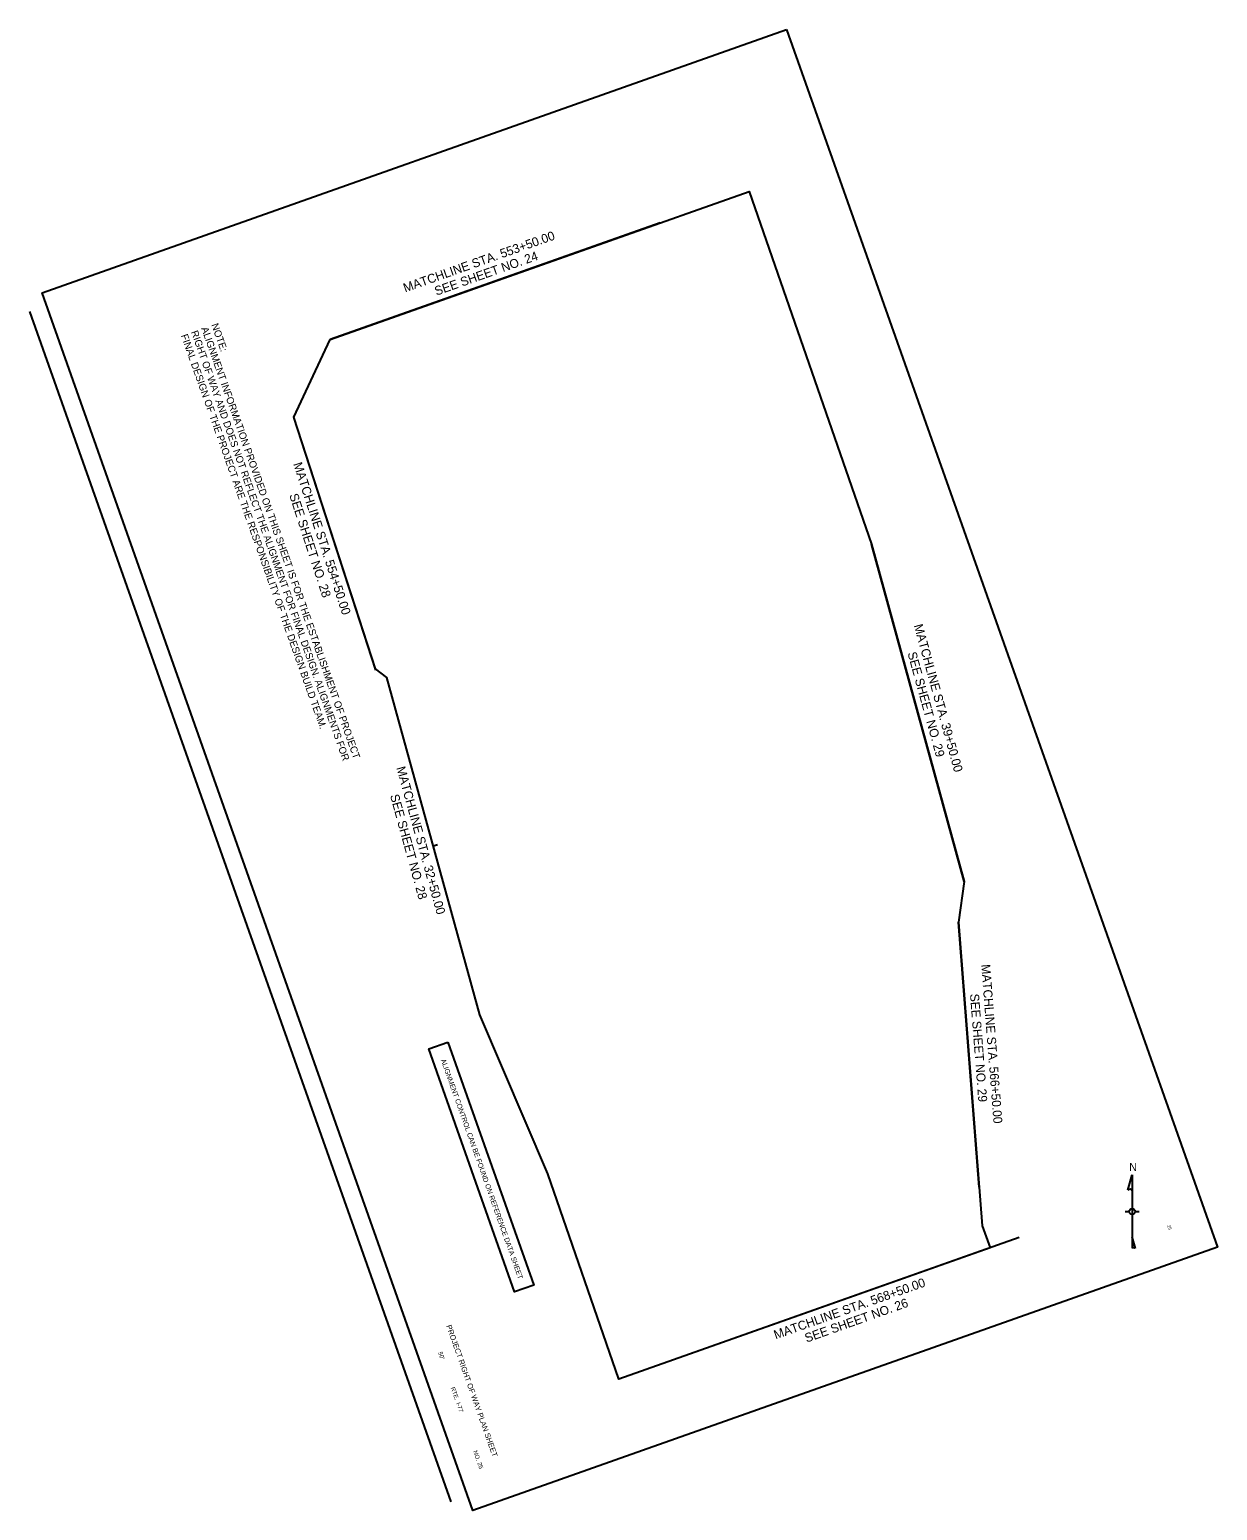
# Model space of a CAD drawing. Extents: x 2005048 to 2006703, y 1136071 to 1138135.
import ezdxf

# ---------------------------------------------------------------- set-up
doc = ezdxf.new("R2010")
doc.units = 0
for name, color, linetype in [('North Arrow', 7, 'Continuous'), ('RD_SHT_IplotShp', 7, 'Continuous'), ('RD_SHT_MatchLine', 7, 'Continuous'), ('RD_SHT_Misc1', 7, 'Continuous'), ('RD_SHT_ShtClip', 7, 'Continuous'), ('RD_SHT_TX', 7, 'Continuous')]:
    doc.layers.add(name, color=color, linetype=linetype)

msp = doc.modelspace()

# ---------------------------------------------------------------- linework, layer by layer
at = {"layer": 'North Arrow'}
for p, q in [((2006577.9, 1136517.4), (2006583.8, 1136538.4)), ((2006583.8, 1136538.4), (2006583.8, 1136516.2)), ((2006583.8, 1136538.4), (2006583.8, 1136436.2)), ((2006574.1, 1136487.3), (2006579.8, 1136487.3)), ((2006587.9, 1136487.3), (2006593.5, 1136487.3)), ((2006583.8, 1136452), (2006583.8, 1136436.2)), ((2006588.4, 1136435.9), (2006583.8, 1136452))]:
    msp.add_line(p, q, dxfattribs=at)
msp.add_circle((2006583.8, 1136487.3), 4.02, dxfattribs=at)
for centre, radius, start, end in [((2006580.5, 1136514.9), 3.59, 22.3707, 136.1387), ((2006586, 1136433.7), 3.3, 43.3397, 130.5607)]:
    msp.add_arc(centre, radius, start, end, dxfattribs=at)
at = {"layer": 'RD_SHT_IplotShp'}
msp.add_line((2005616.2, 1136998.3), (2005610.3, 1136996.7), dxfattribs=at)
msp.add_lwpolyline([(2006102.2, 1138134.7), (2006702.6, 1136437.7), (2005665.5, 1136070.9), (2005065.2, 1137767.8)], close=True, dxfattribs=at)
at = {"layer": 'RD_SHT_MatchLine'}
for p, q in [((2005926.3, 1137865.4), (2005466.7, 1137702.8)), ((2005530, 1137242), (2005415.7, 1137594.3)), ((2006349.9, 1136947.4), (2006220.5, 1137417.4)), ((2005675, 1136761.7), (2005545.6, 1137231.7)), ((2006370.6, 1136521.5), (2006341.8, 1136890.8)), ((2006426.6, 1136451.3), (2005967, 1136288.7))]:
    msp.add_line(p, q, dxfattribs=at)
at = {"layer": 'RD_SHT_ShtClip'}
msp.add_lwpolyline([(2005466.7, 1137702.8), (2006050.1, 1137909.2), (2006220.5, 1137417.4), (2006349.9, 1136947.4), (2006341.8, 1136890.8), (2006374.8, 1136467.3), (2006385.9, 1136436.9), (2005868.7, 1136253.9), (2005769.8, 1136540.1), (2005675, 1136761.7), (2005545.6, 1137231.7), (2005529.5, 1137243.8), (2005415.7, 1137594.3)], close=True, dxfattribs=at)
at = {"layer": 'RD_SHT_TX'}
msp.add_line((2005047.9, 1137741.9), (2005634.8, 1136082.7), dxfattribs=at)
msp.add_line((2005047.9, 1137741.9), (2005634.8, 1136082.7), dxfattribs=at)
msp.add_lwpolyline([(2005630.5, 1136723.4), (2005750.3, 1136384.8), (2005723.5, 1136375.4), (2005603.8, 1136714)], close=True, dxfattribs=at)

# ---------------------------------------------------------------- texts
at = {"layer": 'North Arrow'}
msp.add_text('N', height=11.1, dxfattribs=at).set_placement((2006579.8, 1136543.9))
at = {"layer": 'RD_SHT_MatchLine'}
for s, rotation, p in [('MATCHLINE STA. 553+50.00', 19.482, (2005571, 1137768.3)), ('SEE SHEET NO. 24', 19.482, (2005614.6, 1137763.8)), ('MATCHLINE STA. 554+50.00', 287.9765, (2005415, 1137529.4)), ('SEE SHEET NO. 28', 287.9765, (2005409.4, 1137485.9)), ('MATCHLINE STA. 39+50.00', 285.3889, (2006279.6, 1137304.3)), ('SEE SHEET NO. 29', 285.3889, (2006270.8, 1137265.6)), ('MATCHLINE STA. 32+50.00', 285.3889, (2005558.7, 1137105.9)), ('SEE SHEET NO. 28', 285.3889, (2005549.9, 1137067.2)), ('MATCHLINE STA. 566+50.00', 274.4504, (2006373.5, 1136831.5)), ('SEE SHEET NO. 29', 274.4504, (2006357.9, 1136790.5)), ('MATCHLINE STA. 568+50.00', 19.482, (2006087.2, 1136309.2)), ('SEE SHEET NO. 26', 19.482, (2006130.3, 1136304.6))]:
    msp.add_text(s, height=12.5, rotation=rotation, dxfattribs=at).set_placement(p)
at = {"layer": 'RD_SHT_Misc1'}
for s, p in [('RIGHT OF WAY AND DOES NOT REFLECT THE ALIGNMENT FOR FINAL DESIGN. ALIGNMENTS FOR', (2005272.5, 1137713.3)), ('ALIGNMENT INFORMATION PROVIDED ON THIS SHEET IS FOR THE ESTABLISHMENT OF PROJECT', (2005286.7, 1137718.3)), ('NOTE:', (2005300.8, 1137723.3)), ('FINAL DESIGN OF THE PROJECT ARE THE RESPONSIBILITY OF THE DESIGN BUILD TEAM.', (2005258.4, 1137708.3))]:
    msp.add_text(s, height=10, rotation=289.482, dxfattribs=at).set_placement(p)
at = {"layer": 'RD_SHT_TX'}
for s, height, p in [('ALIGNMENT CONTROL CAN BE FOUND ON REFERENCE DATA SHEET', 7, (2005620.5, 1136698.8)), ('25', 4.5, (2006632.5, 1136467.8)), ('PROJECT RIGHT OF WAY PLAN SHEET', 7.5, (2005628.1, 1136328)), ("50'", 6, (2005616.9, 1136290.8)), ('RTE.', 6, (2005634.3, 1136241.7)), ('I-77', 6, (2005641.9, 1136220.2)), ('NO.', 6, (2005665.6, 1136153.2)), ('25', 6, (2005671.4, 1136136.9))]:
    msp.add_text(s, height=height, rotation=289.482, dxfattribs=at).set_placement(p)

doc.saveas('drawing.dxf')
